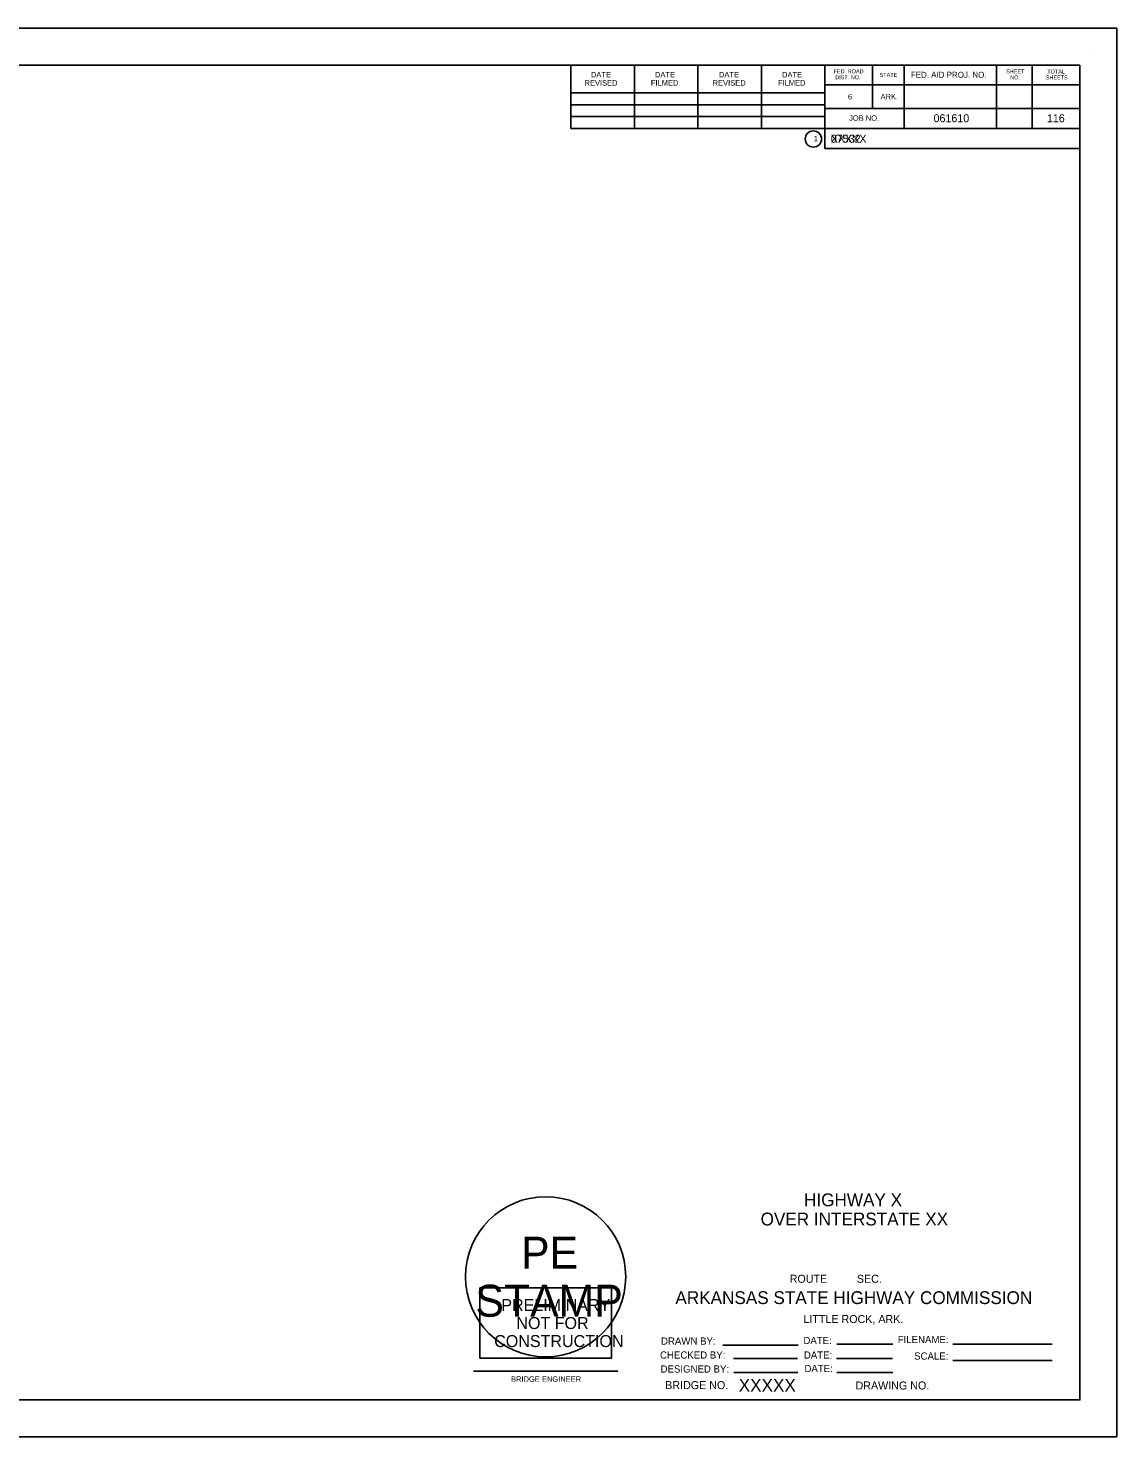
# Model space of a CAD drawing. Extents: x 0 to 2.83, y 0 to 1.83.
# Drawn here: x 1.417 to 2.833, y 0 to 1.833 of the extents above; entities that cross this region are included whole.
import ezdxf

# ---------------------------------------------------------------- set-up
doc = ezdxf.new("R2010")
doc.units = 0
for name, color, linetype in [('B-Block-Border', 7, 'Continuous'), ('B-Gen-Construction Line', 7, 'Continuous'), ('B-Tbl-Bridge B', 7, 'Continuous'), ('B-Tbl-Bridge C', 7, 'Continuous'), ('B-Tbl-Bridge D', 7, 'Continuous'), ('B-Tbl-Bridge E', 7, 'Continuous'), ('B-Tbl-Bridge F', 7, 'Continuous'), ('B-Tbl-Prelim', 7, 'Continuous'), ('B-Tbl-Title Block', 7, 'Continuous'), ('B-Tbl-Title Block Major Text', 7, 'Continuous'), ('B-Tbl-Title Block Minor Text', 7, 'Continuous'), ('B-Title Block (No Plot)', 7, 'Continuous'), ('Default', 7, 'Continuous')]:
    doc.layers.add(name, color=color, linetype=linetype)

msp = doc.modelspace()

# ---------------------------------------------------------------- linework, layer by layer
at = {"layer": 'B-Block-Border'}
msp.add_lwpolyline([(0, 0), (2.8333, 0), (2.8333, 1.8333), (0, 1.8333)], close=True, dxfattribs=at)
at = {"layer": 'B-Gen-Construction Line'}
msp.add_circle((2.09, 0.2083), 0.1042, dxfattribs=at)
at = {"layer": 'B-Tbl-Prelim'}
msp.add_lwpolyline([(2.0042, 0.1937), (2.1758, 0.1937), (2.1758, 0.1025), (2.0042, 0.1025)], close=True, dxfattribs=at)
at = {"layer": 'B-Tbl-Title Block'}
for p, q in [((2.123, 1.7853), (2.123, 1.7027)), ((2.2055, 1.7027), (2.2055, 1.7853)), ((2.288, 1.7027), (2.288, 1.7853)), ((2.3709, 1.7027), (2.3709, 1.7853)), ((2.4534, 1.6769), (2.4534, 1.7853)), ((2.5154, 1.7286), (2.5154, 1.7853)), ((2.5568, 1.7027), (2.5568, 1.7853)), ((2.6769, 1.7853), (2.6769, 1.7027)), ((2.7233, 1.7853), (2.7233, 1.7027)), ((2.4531, 1.7491), (2.123, 1.7491)), ((2.7853, 1.7594), (2.4534, 1.7594)), ((2.4534, 1.7335), (2.123, 1.7335)), ((2.7853, 1.7286), (2.4534, 1.7286)), ((2.4534, 1.7183), (2.123, 1.7183)), ((2.7853, 1.7027), (2.123, 1.7027)), ((2.4534, 1.6769), (2.7853, 1.6769)), ((2.3205, 0.1191), (2.4185, 0.1191)), ((2.4691, 0.1208), (2.542, 0.1208)), ((2.6198, 0.1208), (2.7491, 0.1208)), ((2.3344, 0.102), (2.4177, 0.102)), ((2.4684, 0.102), (2.5413, 0.102)), ((2.6198, 0.0994), (2.7491, 0.0994)), ((1.9963, 0.0853), (2.1838, 0.0853)), ((2.335, 0.0837), (2.4183, 0.0837)), ((2.4691, 0.0837), (2.542, 0.0837))]:
    msp.add_line(p, q, dxfattribs=at)
msp.add_lwpolyline([(2.7853, 1.7853), (0.1263, 1.7853), (0.1263, 0.0481), (2.7853, 0.0481)], close=True, dxfattribs=at)
msp.add_circle((2.4385, 1.6891), 0.0106, dxfattribs=at)
at = {"layer": 'B-Title Block (No Plot)'}
msp.add_line((2.8035, 1.8045), (2.8035, 1.8045), dxfattribs=at)

# ---------------------------------------------------------------- texts
at = {"layer": 'B-Gen-Construction Line'}
for s, p in [('PE ', (2.058, 0.2188)), ('STAMP', (1.9986, 0.1563))]:
    msp.add_text(s, height=0.04167, dxfattribs=at).set_placement(p)
at = {"layer": 'B-Tbl-Bridge B'}
for s, height, p in [('XXXXX', 0.01042, (2.4611, 1.6842)), ('HIGHWAY X', 0.01667, (2.4263, 0.3001)), ('OVER INTERSTATE XX', 0.016667, (2.3698, 0.2751)), ('XXXXX', 0.01667, (2.3413, 0.0587))]:
    msp.add_text(s, height=height, rotation=0, dxfattribs=at).set_placement(p)
at = {"layer": 'B-Tbl-Bridge C'}
for s, height, p in [('XXXXX', 0.01042, (2.4611, 1.6842)), ('HIGHWAY X', 0.01667, (2.4263, 0.3001)), ('OVER INTERSTATE XX', 0.016667, (2.3698, 0.2751)), ('XXXXX', 0.01667, (2.3413, 0.0587))]:
    msp.add_text(s, height=height, rotation=0, dxfattribs=at).set_placement(p)
at = {"layer": 'B-Tbl-Bridge D'}
for s, height, p in [('XXXXX', 0.01042, (2.4611, 1.6842)), ('HIGHWAY X', 0.01667, (2.4263, 0.3001)), ('OVER INTERSTATE XX', 0.016667, (2.3698, 0.2751)), ('XXXXX', 0.01667, (2.3413, 0.0587))]:
    msp.add_text(s, height=height, rotation=0, dxfattribs=at).set_placement(p)
at = {"layer": 'B-Tbl-Bridge E'}
for s, height, p in [('XXXXX', 0.01042, (2.4611, 1.6842)), ('HIGHWAY X', 0.01667, (2.4263, 0.3001)), ('OVER INTERSTATE XX', 0.016667, (2.3698, 0.2751)), ('XXXXX', 0.01667, (2.3413, 0.0587))]:
    msp.add_text(s, height=height, rotation=0, dxfattribs=at).set_placement(p)
at = {"layer": 'B-Tbl-Bridge F'}
for s, height, p in [('XXXXX', 0.01042, (2.4611, 1.6842)), ('HIGHWAY X', 0.01667, (2.4263, 0.3001)), ('OVER INTERSTATE XX', 0.016667, (2.3698, 0.2751)), ('XXXXX', 0.01667, (2.3413, 0.0587))]:
    msp.add_text(s, height=height, rotation=0, dxfattribs=at).set_placement(p)
at = {"layer": 'B-Tbl-Prelim'}
for s, height, p in [('PRELIMINARY', 0.015625, (2.0324, 0.1637)), ('NOT FOR', 0.01562, (2.052, 0.1403)), ('CONSTRUCTION', 0.015625, (2.0231, 0.1168))]:
    msp.add_text(s, height=height, dxfattribs=at).set_placement(p)
at = {"layer": 'B-Tbl-Title Block'}
for s, height, p in [('1', 0.00708, (2.4389, 1.6861)), ('07532', 0.01042, (2.4611, 1.6842)), ('DRAWN BY:', 0.00937, (2.2402, 0.12)), ('DATE:', 0.00937, (2.4255, 0.1207)), ('FILENAME:', 0.00937, (2.5482, 0.1219)), ('CHECKED BY:', 0.009375, (2.2389, 0.1018)), ('DATE:', 0.00937, (2.4261, 0.1018)), ('DESIGNED BY:', 0.009375, (2.2396, 0.0836)), ('DATE:', 0.00937, (2.4268, 0.0842)), ('SCALE:', 0.00937, (2.5696, 0.1005)), ('BRIDGE ENGINEER', 0.007083, (2.045, 0.0716))]:
    msp.add_text(s, height=height, rotation=0, dxfattribs=at).set_placement(p)
at = {"layer": 'B-Tbl-Title Block Major Text'}
for s, height, p in [('ROUTE          SEC.', 0.010417, (2.4076, 0.2005)), ('ARKANSAS STATE HIGHWAY COMMISSION', 0.016667, (2.2589, 0.1728)), ('LITTLE ROCK, ARK.', 0.010417, (2.4255, 0.1481))]:
    msp.add_text(s, height=height, rotation=0, dxfattribs=at).set_placement(p)
at = {"layer": 'B-Tbl-Title Block Minor Text'}
for s, height, p in [('FED. ROAD', 0.00517, (2.4649, 1.7746)), ('SHEET', 0.00517, (2.6893, 1.7744)), ('TOTAL', 0.00517, (2.7429, 1.7743)), ('REVISED', 0.00708, (2.1407, 1.7586)), ('DATE', 0.00708, (2.149, 1.7693)), ('FILMED', 0.00708, (2.227, 1.7586)), ('DATE', 0.00708, (2.2323, 1.7693)), ('REVISED', 0.00708, (2.3074, 1.7586)), ('DATE', 0.00708, (2.3156, 1.7693)), ('FILMED', 0.00708, (2.3924, 1.7586)), ('DATE', 0.00708, (2.3977, 1.7693)), ('DIST. NO.', 0.00517, (2.4669, 1.7669)), ('STATE', 0.00517, (2.5246, 1.77)), ('FED. AID PROJ. NO.', 0.00775, (2.5653, 1.7688)), ('NO.', 0.00517, (2.6946, 1.7666)), ('SHEETS', 0.00517, (2.7409, 1.7666)), ('6', 0.00708, (2.4835, 1.7407)), ('ARK.', 0.00708, (2.5259, 1.7407)), ('JOB NO.', 0.00708, (2.4849, 1.7128)), ('061610', 0.01042, (2.5948, 1.7109)), ('116', 0.01042, (2.7423, 1.7109))]:
    msp.add_text(s, height=height, rotation=0, dxfattribs=at).set_placement(p)
at = {"layer": 'Default'}
for s, height, p in [('BRIDGE NO.', 0.01042, (2.2456, 0.0621)), ('DRAWING NO.', 0.010417, (2.4933, 0.0616))]:
    msp.add_text(s, height=height, rotation=0, dxfattribs=at).set_placement(p)

doc.saveas('drawing.dxf')
